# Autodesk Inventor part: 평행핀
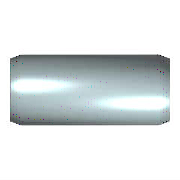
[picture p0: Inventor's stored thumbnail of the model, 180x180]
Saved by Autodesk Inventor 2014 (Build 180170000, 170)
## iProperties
IsCustomPart: 0
Created: 2009-02
Part Number: 평행핀
Material: 강, 연강
Description: 평행 핀
Document SubType Name: Modeling
Standard: KS B 1320
Designer: KYOUNG IL JANG
Standards Organization: KS
Language: ko-KR
Size Designation: B 5 x  20
Categories: <MemberInstance><Categories><Category DisplayName="조임쇠" InternalName="e4da775c-781d-43d5-af7c-5136215cf5a6" Mnemonic="FSTN"><Category DisplayName="핀" InternalNa
Density: 1 g/cm^3
Appearance: 강철
Author: KYOUNG IL JANG
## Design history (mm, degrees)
sketch "스케치"
  geometry: C1 r 2.5 at (0, 0); 1 further point
  constraints: 1 centre point, 1 coincident
  dimensions: "d1" = 5 diameter of C1 (= NND)
extrude "본체" new body sketch "스케치" distance "d2" = 20 (= NLG); taper "d3" = 0 deg
chamfer "스케치2" distance "d8" = 0.8 (= PHH); stored, may be unused: angle "d9" = 15 deg (= FAWI), second distance "d12" = 0.8 (= PHH)
body "Solid1"
chamfer "모따기1" distance "d4" = 0.8 (= PHH); stored, may be unused: angle "d5" = 15 deg (= FAWI), second distance "d11" = 0.8 (= PHH)
other parameters: "NND" = 5 [user parameter; used in 1 equation term], "NLG" = 20 [user parameter; used in 1 equation term], "PHH" = 0.8 [user parameter; used in 4 equation terms], "FAWI" = 15 deg [user parameter; used in 2 equation terms], "d13" = 0, "d15" = 0, "d16" = 0, "KAH" = 0.63 [user parameter]
